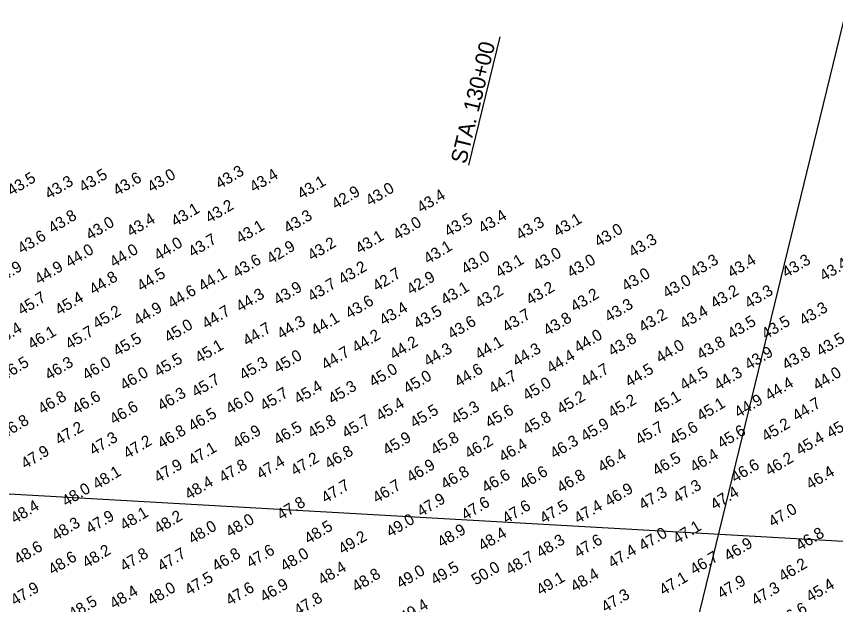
# Model space of a CAD drawing. Extents: x 415488 to 419888, y 1187739 to 1191312.
# Drawn here: x 416796 to 417516, y 1189998 to 1190515 of the extents above; entities that cross this region are included whole.
import ezdxf

# ---------------------------------------------------------------- set-up
doc = ezdxf.new("R2010")
doc.units = 0
for name, color, linetype in [('C-CHAN-WIDE', 7, 'Continuous'), ('V-ALGN-TEXT', 7, 'Continuous'), ('V-TOPO-SOUN', 7, 'Continuous')]:
    doc.layers.add(name, color=color, linetype=linetype)

msp = doc.modelspace()

# ---------------------------------------------------------------- linework, layer by layer
at = {"layer": 'C-CHAN-WIDE'}
msp.add_line((416205.49, 1190128.89), (418985.51, 1189971.03), dxfattribs=at)
at = {"layer": 'V-ALGN-TEXT'}
for p, q in [((417252.51, 1189399.35), (417536.93, 1190565.61)), ((417194.13, 1190384.23), (417221.66, 1190497.12))]:
    msp.add_line(p, q, dxfattribs=at)

# ---------------------------------------------------------------- texts
msp.add_text('STA. 130+00', height=13.92, rotation=76.29456, dxfattribs=at).set_placement((417191.41, 1190384.81))
at = {"layer": 'V-TOPO-SOUN'}
for s, p in [('43.5 ', (416855.1, 1190359.97)), ('43.0 ', (416915.11, 1190359.97)), ('43.3 ', (416975.08, 1190362.99)), ('43.4 ', (417005.1, 1190359.97)), ('43.5 ', (416792.08, 1190356.99)), ('43.3 ', (416825.08, 1190353.97)), ('43.6 ', (416885.09, 1190356.99)), ('43.1 ', (417047.1, 1190353.97)), ('42.9 ', (417077.08, 1190344.98)), ('43.0 ', (417107.1, 1190348)), ('43.4 ', (417152.08, 1190341.99)), ('43.1 ', (416936.11, 1190329.98)), ('43.2 ', (416966.09, 1190332.97)), ('43.8 ', (416828.1, 1190323.98)), ('43.3 ', (417035.09, 1190323.98)), ('43.4 ', (417206.09, 1190323.98)), ('43.0 ', (416861.11, 1190317.98)), ('43.4 ', (416897.1, 1190320.99)), ('43.0 ', (417131.09, 1190317.98)), ('43.5 ', (417176.1, 1190320.99)), ('43.3 ', (417239.09, 1190317.98)), ('43.1 ', (417272.1, 1190320.99)), ('43.1 ', (416993.09, 1190314.99)), ('43.0 ', (417308.09, 1190311.97)), ('43.6 ', (416801.1, 1190305.97)), ('43.7 ', (416951.1, 1190302.98)), ('43.1 ', (417098.08, 1190305.97)), ('43.3 ', (417338.11, 1190302.98)), ('44.0 ', (416843.09, 1190293.99)), ('44.0 ', (416882.1, 1190293.99)), ('44.0 ', (416921.08, 1190300)), ('42.9 ', (417020.1, 1190296.98)), ('43.2 ', (417056.09, 1190300)), ('43.1 ', (417158.09, 1190296.98)), ('43.0 ', (417191.09, 1190287.99)), ('43.0 ', (417254.08, 1190290.97)), ('44.9 ', (416780.1, 1190278.97)), ('44.9 ', (416816.09, 1190278.97)), ('43.6 ', (416990.11, 1190284.97)), ('43.1 ', (417221.08, 1190284.97)), ('43.0 ', (417284.1, 1190284.97)), ('43.3 ', (417392.11, 1190284.97)), ('43.4 ', (417425.08, 1190284.97)), ('43.3 ', (417473.08, 1190284.97)), ('43.4 ', (417506.09, 1190281.99)), ('44.5 ', (416906.09, 1190273)), ('44.1 ', (416960.09, 1190273)), ('43.2 ', (417083.09, 1190278.97)), ('42.7 ', (417113.11, 1190273)), ('43.0 ', (417332.1, 1190273)), ('44.8 ', (416864.09, 1190269.98)), ('43.7 ', (417056.09, 1190263.97)), ('42.9 ', (417143.09, 1190269.98)), ('43.0 ', (417368.09, 1190266.99)), ('44.6 ', (416933.09, 1190257.97)), ('43.9 ', (417026.1, 1190260.99)), ('43.1 ', (417173.08, 1190260.99)), ('43.2 ', (417203.1, 1190257.97)), ('43.2 ', (417248.08, 1190260.99)), ('43.2 ', (417410.09, 1190257.97)), ('43.3 ', (417440.11, 1190257.97)), ('45.7 ', (416801.1, 1190252)), ('45.4 ', (416834.1, 1190252)), ('44.3 ', (416993.09, 1190254.98)), ('43.2 ', (417287.09, 1190254.98)), ('44.9 ', (416903.1, 1190242.98)), ('43.6 ', (417089.09, 1190248.98)), ('43.4 ', (417119.08, 1190242.98)), ('43.3 ', (417317.11, 1190245.99)), ('45.2 ', (416867.11, 1190239.99)), ('44.7 ', (416963.11, 1190239.99)), ('43.5 ', (417149.1, 1190239.99)), ('43.7 ', (417227.08, 1190236.97)), ('43.2 ', (417347.1, 1190236.97)), ('43.4 ', (417383.09, 1190239.99)), ('43.3 ', (417488.11, 1190242.98)), ('44.3 ', (417029.08, 1190230.97)), ('44.1 ', (417059.1, 1190233.99)), ('43.6 ', (417179.08, 1190230.97)), ('43.8 ', (417263.11, 1190233.99)), ('43.5 ', (417425.08, 1190230.97)), ('43.5 ', (417455.1, 1190230.97)), ('46.4 ', (416780.1, 1190225)), ('46.1 ', (416810.09, 1190221.98)), ('45.7 ', (416843.09, 1190221.98)), ('45.0 ', (416930.1, 1190227.98)), ('44.7 ', (416999.1, 1190225)), ('45.5 ', (416885.09, 1190215.97)), ('44.2 ', (417095.1, 1190218.99)), ('44.0 ', (417290.11, 1190218.99)), ('43.8 ', (417320.09, 1190215.97)), ('43.5 ', (417503.1, 1190215.97)), ('45.1 ', (416957.1, 1190209.97)), ('44.2 ', (417128.1, 1190212.99)), ('44.1 ', (417203.1, 1190212.99)), ('44.0 ', (417362.09, 1190209.97)), ('43.8 ', (417398.08, 1190212.99)), ('45.0 ', (417026.1, 1190200.98)), ('44.7 ', (417068.09, 1190203.97)), ('44.3 ', (417158.09, 1190206.99)), ('44.3 ', (417236.11, 1190206.99)), ('44.4 ', (417266.09, 1190200.98)), ('43.9 ', (417440.11, 1190203.97)), ('43.8 ', (417473.08, 1190203.97)), ('46.5 ', (416786.11, 1190194.98)), ('46.3 ', (416825.08, 1190194.98)), ('46.0 ', (416858.09, 1190194.98)), ('45.5 ', (416921.08, 1190198)), ('45.3 ', (416996.08, 1190194.98)), ('46.0 ', (416891.09, 1190185.99)), ('45.0 ', (417110.09, 1190188.97)), ('44.6 ', (417185.09, 1190188.97)), ('44.7 ', (417296.08, 1190188.97)), ('44.5 ', (417335.09, 1190188.97)), ('44.5 ', (417383.09, 1190185.99)), ('44.3 ', (417413.11, 1190185.99)), ('44.0 ', (417500.08, 1190185.99)), ('45.7 ', (416954.09, 1190179.98)), ('45.0 ', (417140.11, 1190182.97)), ('44.7 ', (417215.11, 1190182.97)), ('45.4 ', (417044.08, 1190173.98)), ('45.3 ', (417074.1, 1190173.98)), ('45.0 ', (417245.09, 1190177)), ('44.4 ', (417458.09, 1190177)), ('46.8 ', (416819.08, 1190164.99)), ('46.6 ', (416849.1, 1190164.99)), ('46.3 ', (416924.1, 1190167.98)), ('46.0 ', (416984.1, 1190164.99)), ('45.7 ', (417014.09, 1190167.98)), ('45.2 ', (417275.08, 1190164.99)), ('45.1 ', (417359.1, 1190164.99)), ('45.4 ', (417116.09, 1190158.99)), ('45.2 ', (417320.09, 1190161.97)), ('45.1 ', (417398.08, 1190158.99)), ('44.9 ', (417431.09, 1190161.97)), ('44.7 ', (417482.1, 1190158.99)), ('46.6 ', (416882.1, 1190155.97)), ('46.5 ', (416951.1, 1190150)), ('45.5 ', (417146.08, 1190152.98)), ('45.3 ', (417182.1, 1190155.97)), ('45.6 ', (417212.09, 1190152.98)), ('46.8 ', (416786.11, 1190143.99)), ('45.8 ', (417056.09, 1190143.99)), ('45.7 ', (417086.11, 1190143.99)), ('45.8 ', (417245.09, 1190146.98)), ('45.0 ', (417512.09, 1190143.99)), ('47.2 ', (416834.1, 1190137.99)), ('46.9 ', (416990.11, 1190134.97)), ('46.5 ', (417026.1, 1190137.99)), ('45.9 ', (417296.08, 1190140.98)), ('45.7 ', (417344.08, 1190137.99)), ('45.6 ', (417374.1, 1190137.99)), ('45.6 ', (417416.09, 1190134.97)), ('45.2 ', (417455.1, 1190140.98)), ('47.3 ', (416864.09, 1190128.97)), ('46.8 ', (416924.1, 1190134.97)), ('45.9 ', (417122.1, 1190128.97)), ('45.8 ', (417164.09, 1190128.97)), ('45.4 ', (417485.09, 1190128.97)), ('47.2 ', (416894.08, 1190125.98)), ('46.2 ', (417194.08, 1190125.98)), ('46.4 ', (417224.1, 1190123)), ('46.3 ', (417269.08, 1190125.98)), ('47.9 ', (416804.09, 1190116.99)), ('47.1 ', (416951.1, 1190119.98)), ('46.8 ', (417071.08, 1190116.99)), ('46.4 ', (417311.11, 1190113.97)), ('46.4 ', (417392.11, 1190113.97)), ('47.4 ', (417011.11, 1190107.97)), ('47.2 ', (417041.09, 1190110.99)), ('46.5 ', (417359.1, 1190110.99)), ('46.2 ', (417458.09, 1190110.99)), ('47.9 ', (416921.08, 1190104.98)), ('47.8 ', (416978.1, 1190104.98)), ('46.9 ', (417143.09, 1190104.98)), ('46.6 ', (417242.11, 1190098.98)), ('46.6 ', (417428.1, 1190104.98)), ('46.4 ', (417494.11, 1190098.98)), ('48.1 ', (416867.11, 1190098.98)), ('46.8 ', (417173.08, 1190098.98)), ('46.6 ', (417209.1, 1190095.99)), ('46.8 ', (417275.08, 1190095.99)), ('48.4 ', (416948.08, 1190089.99)), ('47.7 ', (417068.09, 1190086.97)), ('46.7 ', (417113.11, 1190086.97)), ('47.3 ', (417377.08, 1190086.97)), ('48.0 ', (416840.11, 1190083.99)), ('46.9 ', (417317.11, 1190083.99)), ('47.3 ', (417347.1, 1190080.97)), ('47.4 ', (417410.09, 1190080.97)), ('47.8 ', (417029.08, 1190071.98)), ('47.9 ', (417152.08, 1190075)), ('47.6 ', (417191.09, 1190071.98)), ('48.4 ', (416795.1, 1190068.99)), ('47.6 ', (417227.08, 1190068.99)), ('47.5 ', (417260.09, 1190068.99)), ('47.4 ', (417290.11, 1190068.99)), ('47.0 ', (417461.11, 1190065.98)), ('47.9 ', (416861.11, 1190059.97)), ('48.1 ', (416891.09, 1190062.99)), ('48.2 ', (416921.08, 1190059.97)), ('48.0 ', (416984.1, 1190056.99)), ('49.0 ', (417125.08, 1190056.99)), ('48.3 ', (416831.09, 1190053.97)), ('48.0 ', (416951.1, 1190050.98)), ('48.5 ', (417053.1, 1190050.98)), ('47.1 ', (417377.08, 1190050.98)), ('49.2 ', (417083.09, 1190041.99)), ('48.9 ', (417170.1, 1190048)), ('48.4 ', (417206.09, 1190044.98)), ('47.0 ', (417347.1, 1190044.98)), ('46.8 ', (417485.09, 1190044.98)), ('48.3 ', (417257.1, 1190038.97)), ('47.6 ', (417290.11, 1190038.97)), ('46.9 ', (417422.1, 1190035.99)), ('48.6 ', (416798.08, 1190032.97)), ('48.2 ', (416858.09, 1190029.98)), ('47.7 ', (416924.1, 1190026.97)), ('47.6 ', (417002.08, 1190029.98)), ('48.0 ', (417032.1, 1190026.97)), ('47.4 ', (417320.09, 1190029.98)), ('48.6 ', (416828.1, 1190023.98)), ('47.8 ', (416891.09, 1190026.97)), ('46.8 ', (416972.1, 1190026.97)), ('48.7 ', (417230.1, 1190023.98)), ('46.7 ', (417392.11, 1190023.98)), ('48.4 ', (417065.11, 1190014.99)), ('49.5 ', (417164.09, 1190014.99)), ('50.0 ', (417200.08, 1190014.99)), ('46.2 ', (417470.09, 1190017.98)), ('47.5 ', (416948.08, 1190005.97)), ('48.8 ', (417095.1, 1190008.99)), ('49.0 ', (417134.1, 1190011.97)), ('49.1 ', (417257.1, 1190005.97)), ('48.4 ', (417287.09, 1190008.99)), ('47.1 ', (417365.11, 1190005.97)), ('46.9 ', (417014.09, 1190000)), ('47.9 ', (417416.09, 1190002.98)), ('45.4 ', (417494.11, 1190000)), ('47.9 ', (416795.1, 1189996.98)), ('48.4 ', (416882.1, 1189993.99)), ('48.0 ', (416915.11, 1189996.98)), ('47.6 ', (416984.1, 1189996.98)), ('47.3 ', (417446.08, 1189996.98)), ('48.5 ', (416846.08, 1189984.97)), ('47.8 ', (417044.08, 1189987.99)), ('47.3 ', (417314.09, 1189990.98)), ('49.4 ', (417137.09, 1189981.99)), ('46.6 ', (417470.09, 1189978.97))]:
    msp.add_text(s, height=9.996, rotation=31.2939, dxfattribs=at).set_placement(p)

doc.saveas('drawing.dxf')
